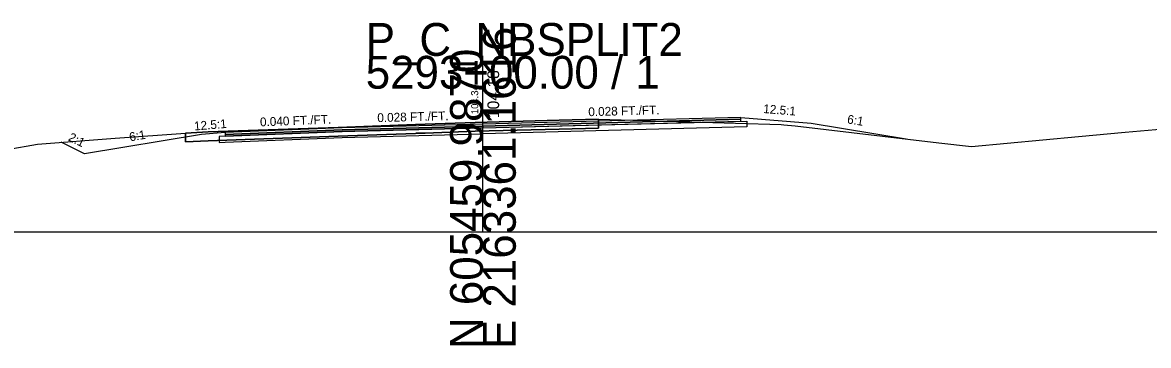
# Model space of a CAD drawing. Extents: x -26 to 1303, y -10 to 12038.
# Drawn here: x 110.7 to 206.8, y 6990.3 to 7017.8 of the extents above; entities that cross this region are included whole.
import ezdxf

# ---------------------------------------------------------------- set-up
doc = ezdxf.new("R2010")
doc.units = 0
for name, color, linetype in [('RD_GPK_XS_Cell', 7, 'Continuous'), ('RD_XS_Base', 7, 'Continuous'), ('RD_XS_ExGround', 7, 'Continuous'), ('RD_XS_ExPaveRet', 7, 'Continuous'), ('RD_XS_Greenside', 7, 'Continuous'), ('RD_XS_Pave', 7, 'Continuous'), ('RD_XS_PaveOvlay_CP', 7, 'Continuous'), ('RD_XS_TieSlope', 7, 'Continuous'), ('RD_XS_TX_Elev_EX', 7, 'Continuous'), ('RD_XS_TX_Elev_PR', 7, 'Continuous'), ('RD_XS_TX_ShdSlope', 7, 'Continuous'), ('RD_XS_TX_Slope', 7, 'Continuous')]:
    doc.layers.add(name, color=color, linetype=linetype)

msp = doc.modelspace()

# ---------------------------------------------------------------- linework, layer by layer
at = {"layer": 'RD_GPK_XS_Cell'}
for p, q in [((150, 7000), (150, 7015)), ((0, 7000), (150, 7000)), ((150, 7000), (300, 7000))]:
    msp.add_line(p, q, dxfattribs=at)
at = {"layer": 'RD_XS_Base'}
for p, q in [((138, 7008.547), (128, 7008.147)), ((150, 7008.859), (138, 7008.547)), ((138, 7008.547), (138, 7008.547)), ((150, 7008.859), (172.5, 7009.444)), ((150, 7008.359), (150, 7009.018)), ((150, 7009.018), (150, 7009.018)), ((150, 7009.018), (150, 7009.018)), ((150, 7009.018), (150, 7008.859)), ((172.5, 7008.944), (150, 7008.359)), ((150, 7008.859), (150, 7008.859)), ((150, 7008.359), (150, 7008.859)), ((150, 7008.859), (150, 7008.859)), ((150, 7008.859), (150, 7008.859)), ((172, 7009.431), (172, 7009.431)), ((172, 7009.431), (172, 7009.431)), ((172, 7009.431), (172, 7009.431)), ((172, 7008.931), (172, 7008.931)), ((172, 7008.931), (172, 7008.931)), ((172.5, 7009.444), (172.5, 7008.944)), ((172.5, 7009.411), (172.5, 7009.411)), ((128, 7008.147), (127.5, 7008.127)), ((127.5, 7008.127), (127.5, 7008.127)), ((127.5, 7008.127), (127.5, 7007.627)), ((127.5, 7007.627), (128, 7007.647)), ((128, 7008.147), (128, 7008.147)), ((128, 7007.647), (138, 7008.047)), ((128, 7007.647), (128, 7007.647)), ((138, 7008.047), (150, 7008.359)), ((138, 7008.047), (138, 7008.047)), ((150, 7008.359), (150, 7008.359))]:
    msp.add_line(p, q, dxfattribs=at)
at = {"layer": 'RD_XS_ExGround'}
msp.add_lwpolyline([(106.807, 7006.555), (112.009, 7007.484), (118.611, 7007.985), (124.623, 7008.415), (126.571, 7008.519), (137.651, 7008.903), (144.242, 7009.144), (144.292, 7009.148), (145.06, 7009.172), (149.348, 7009.323), (149.351, 7009.323), (156.503, 7009.509), (159.846, 7009.589), (175.431, 7009.15), (175.684, 7009.133), (176.645, 7009.022), (188.9, 7007.591), (191.679, 7007.263), (200.807, 7008.138), (204.783, 7008.5), (215.247, 7009.397)], dxfattribs=at)
at = {"layer": 'RD_XS_ExPaveRet'}
for points in [[(159.846, 7009.589), (159.846, 7009.589), (159.846, 7008.839), (159.846, 7008.839), (159.846, 7008.839), (156.503, 7008.759), (156.503, 7008.759), (149.351, 7008.573), (149.351, 7008.573), (149.348, 7008.573), (149.348, 7008.573), (145.06, 7008.422), (145.06, 7008.422), (144.292, 7008.398), (144.242, 7008.394), (144.242, 7008.394), (137.651, 7008.153), (137.651, 7008.153), (126.571, 7007.769), (126.571, 7007.769), (124.623, 7007.665), (124.623, 7007.665), (124.623, 7008.415), (124.623, 7008.415), (124.623, 7008.415), (126.571, 7008.519), (126.571, 7008.519), (137.651, 7008.903), (137.651, 7008.903), (144.242, 7009.144), (144.242, 7009.144), (144.292, 7009.148), (145.06, 7009.172), (145.06, 7009.172), (149.348, 7009.323), (149.348, 7009.323), (149.351, 7009.323), (149.351, 7009.323), (156.503, 7009.509), (156.503, 7009.509), (159.846, 7009.589), (159.846, 7009.589), (159.846, 7009.589)], [(159.846, 7009.589), (156.503, 7009.509), (149.351, 7009.323), (149.348, 7009.323), (145.06, 7009.172), (144.292, 7009.148), (144.242, 7009.144), (137.651, 7008.903), (126.571, 7008.519), (124.623, 7008.415), (124.623, 7007.665), (126.571, 7007.769), (137.651, 7008.153), (144.242, 7008.394), (144.292, 7008.398), (145.06, 7008.422), (149.348, 7008.573), (149.351, 7008.573), (156.503, 7008.759), (159.846, 7008.839)], [(159.846, 7008.839), (159.846, 7009.589), (159.846, 7009.589)], [(159.846, 7008.839), (159.846, 7008.839)]]:
    msp.add_lwpolyline(points, dxfattribs=at)
at = {"layer": 'RD_XS_Greenside'}
for p, q in [((178, 7009.269), (186.12, 7007.915)), ((116, 7006.638), (114.006, 7007.635)), ((126, 7008.305), (116, 7006.638))]:
    msp.add_line(p, q, dxfattribs=at)
at = {"layer": 'RD_XS_Pave'}
for p, q in [((172, 7009.749), (150, 7009.177)), ((172, 7009.59), (150, 7009.018)), ((150, 7009.018), (172, 7009.59)), ((172, 7009.59), (172, 7009.749)), ((172, 7009.749), (172, 7009.749)), ((172, 7009.749), (172, 7009.749)), ((172, 7009.749), (172, 7009.749)), ((172, 7009.431), (172, 7009.59)), ((172, 7009.59), (172, 7009.59)), ((172, 7009.59), (172, 7009.59)), ((172, 7009.59), (172, 7009.59)), ((172, 7009.59), (172, 7009.59)), ((172, 7009.59), (172, 7009.59)), ((138, 7008.865), (128, 7008.465)), ((128, 7008.306), (138, 7008.706)), ((138, 7008.706), (128, 7008.306)), ((128, 7008.147), (138, 7008.547)), ((150, 7009.177), (138, 7008.865)), ((138, 7008.706), (150, 7009.018)), ((150, 7009.018), (138, 7008.706)), ((138, 7008.865), (138, 7008.865)), ((138, 7008.547), (150, 7008.859)), ((138, 7008.706), (138, 7008.706)), ((138, 7008.706), (138, 7008.706)), ((138, 7008.547), (138, 7008.547)), ((150, 7008.859), (172, 7009.431)), ((150, 7009.177), (150, 7009.177)), ((150, 7009.018), (150, 7009.018)), ((150, 7009.018), (150, 7009.018)), ((150, 7009.018), (150, 7008.859)), ((150, 7009.018), (150, 7009.018)), ((150, 7008.859), (150, 7009.018)), ((150, 7009.018), (150, 7009.018)), ((150, 7009.018), (150, 7009.018)), ((150, 7008.859), (150, 7008.859)), ((150, 7008.859), (150, 7008.859)), ((172, 7009.431), (172, 7009.431)), ((172, 7009.431), (172, 7009.431)), ((128, 7008.465), (128, 7008.465)), ((128, 7008.465), (128, 7008.306)), ((128, 7008.306), (128, 7008.306)), ((128, 7008.306), (128, 7008.147))]:
    msp.add_line(p, q, dxfattribs=at)
at = {"layer": 'RD_XS_PaveOvlay_CP'}
for p, q in [((172, 7009.749), (150, 7009.177)), ((172, 7009.749), (172, 7009.749)), ((172, 7009.749), (172, 7009.749)), ((138, 7008.865), (128, 7008.465)), ((150, 7009.177), (138, 7008.865)), ((138, 7008.865), (138, 7008.865)), ((150, 7009.177), (150, 7009.177))]:
    msp.add_line(p, q, dxfattribs=at)
at = {"layer": 'RD_XS_TieSlope'}
for p, q in [((172, 7009.749), (178, 7009.269)), ((128, 7008.465), (126, 7008.305))]:
    msp.add_line(p, q, dxfattribs=at)

# ---------------------------------------------------------------- texts
at = {"layer": 'RD_GPK_XS_Cell'}
for s, p in [('P_C_NBSPLIT2', (140, 7015)), ('5293+00.00 / 1', (140, 7012.2))]:
    msp.add_text(s, height=2.8, dxfattribs=at).set_placement(p)
for s, p in [('E 2163361.1616', (152.8, 6990)), ('N 605459.9870', (150, 6990))]:
    msp.add_text(s, height=2.8, rotation=90, dxfattribs=at).set_placement(p)
at = {"layer": 'RD_XS_TX_Elev_EX'}
msp.add_text('104.34', height=0.6, rotation=90, dxfattribs=at).set_placement((149.596, 7010.036))
at = {"layer": 'RD_XS_TX_Elev_PR'}
msp.add_text('104.18', height=1, rotation=90, dxfattribs=at).set_placement((151.382, 7009.688))
at = {"layer": 'RD_XS_TX_ShdSlope'}
for rotation, p in [(355.42608, (173.893, 7010.129)), (4.57392, (125.384, 7008.635))]:
    msp.add_text('12.5:1', height=0.75, rotation=rotation, dxfattribs=at).set_placement(p)
at = {"layer": 'RD_XS_TX_Slope'}
for s, rotation, p in [('0.028 FT./FT.', 1.60386, (158.999, 7009.853)), ('0.040 FT./FT.', 2.29061, (130.995, 7008.985)), ('0.028 FT./FT.', 1.60386, (140.999, 7009.349)), ('6:1', 350.53582, (181.034, 7009.254)), ('6:1', 9.46418, (119.893, 7007.706)), ('2:1', 333.43495, (114.558, 7007.822))]:
    msp.add_text(s, height=0.75, rotation=rotation, dxfattribs=at).set_placement(p)

doc.saveas('drawing.dxf')
